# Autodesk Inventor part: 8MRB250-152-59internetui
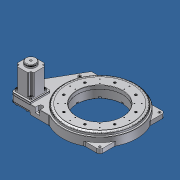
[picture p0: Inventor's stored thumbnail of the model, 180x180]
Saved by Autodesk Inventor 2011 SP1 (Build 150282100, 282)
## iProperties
Created: 2011-12
Part Number: 8MRB250-152-59internetui
Document SubType Name: Modeling
Designer: Darius
Density: 1 g/cm^3
Author: Darius
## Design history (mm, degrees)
feature "Base1"
body "Solid1"
